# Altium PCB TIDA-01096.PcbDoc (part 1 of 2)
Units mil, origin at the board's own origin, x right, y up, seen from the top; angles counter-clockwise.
Board outline 3070.87 x 3070.87 mil, 2 copper layers (Top Layer, Bottom Layer), stack 62 mil thick; 117 components, 49 nets, 258 pads, 158 vias.
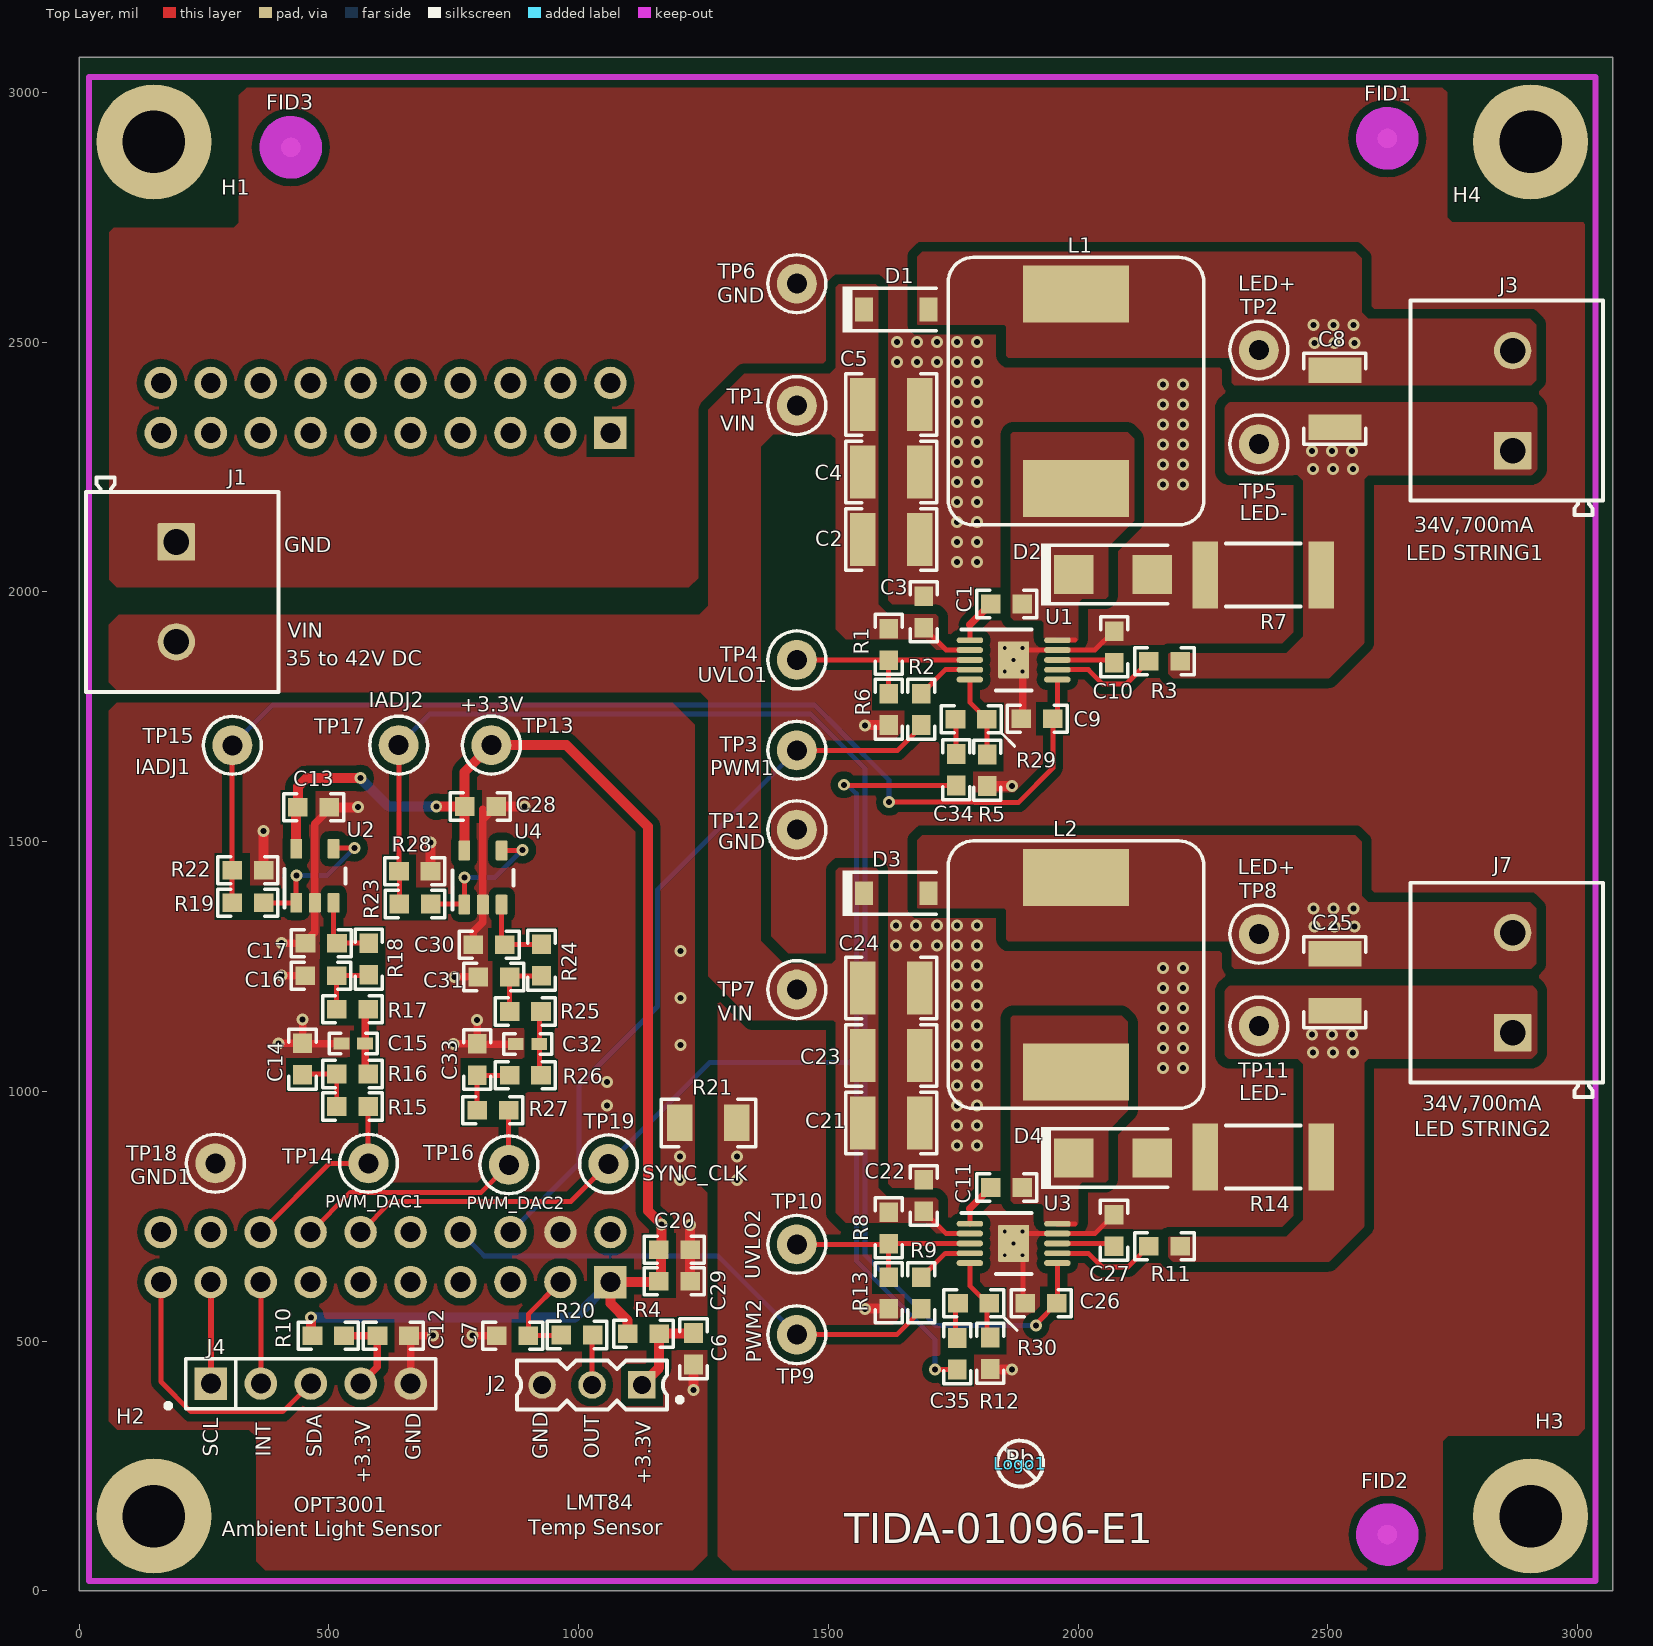
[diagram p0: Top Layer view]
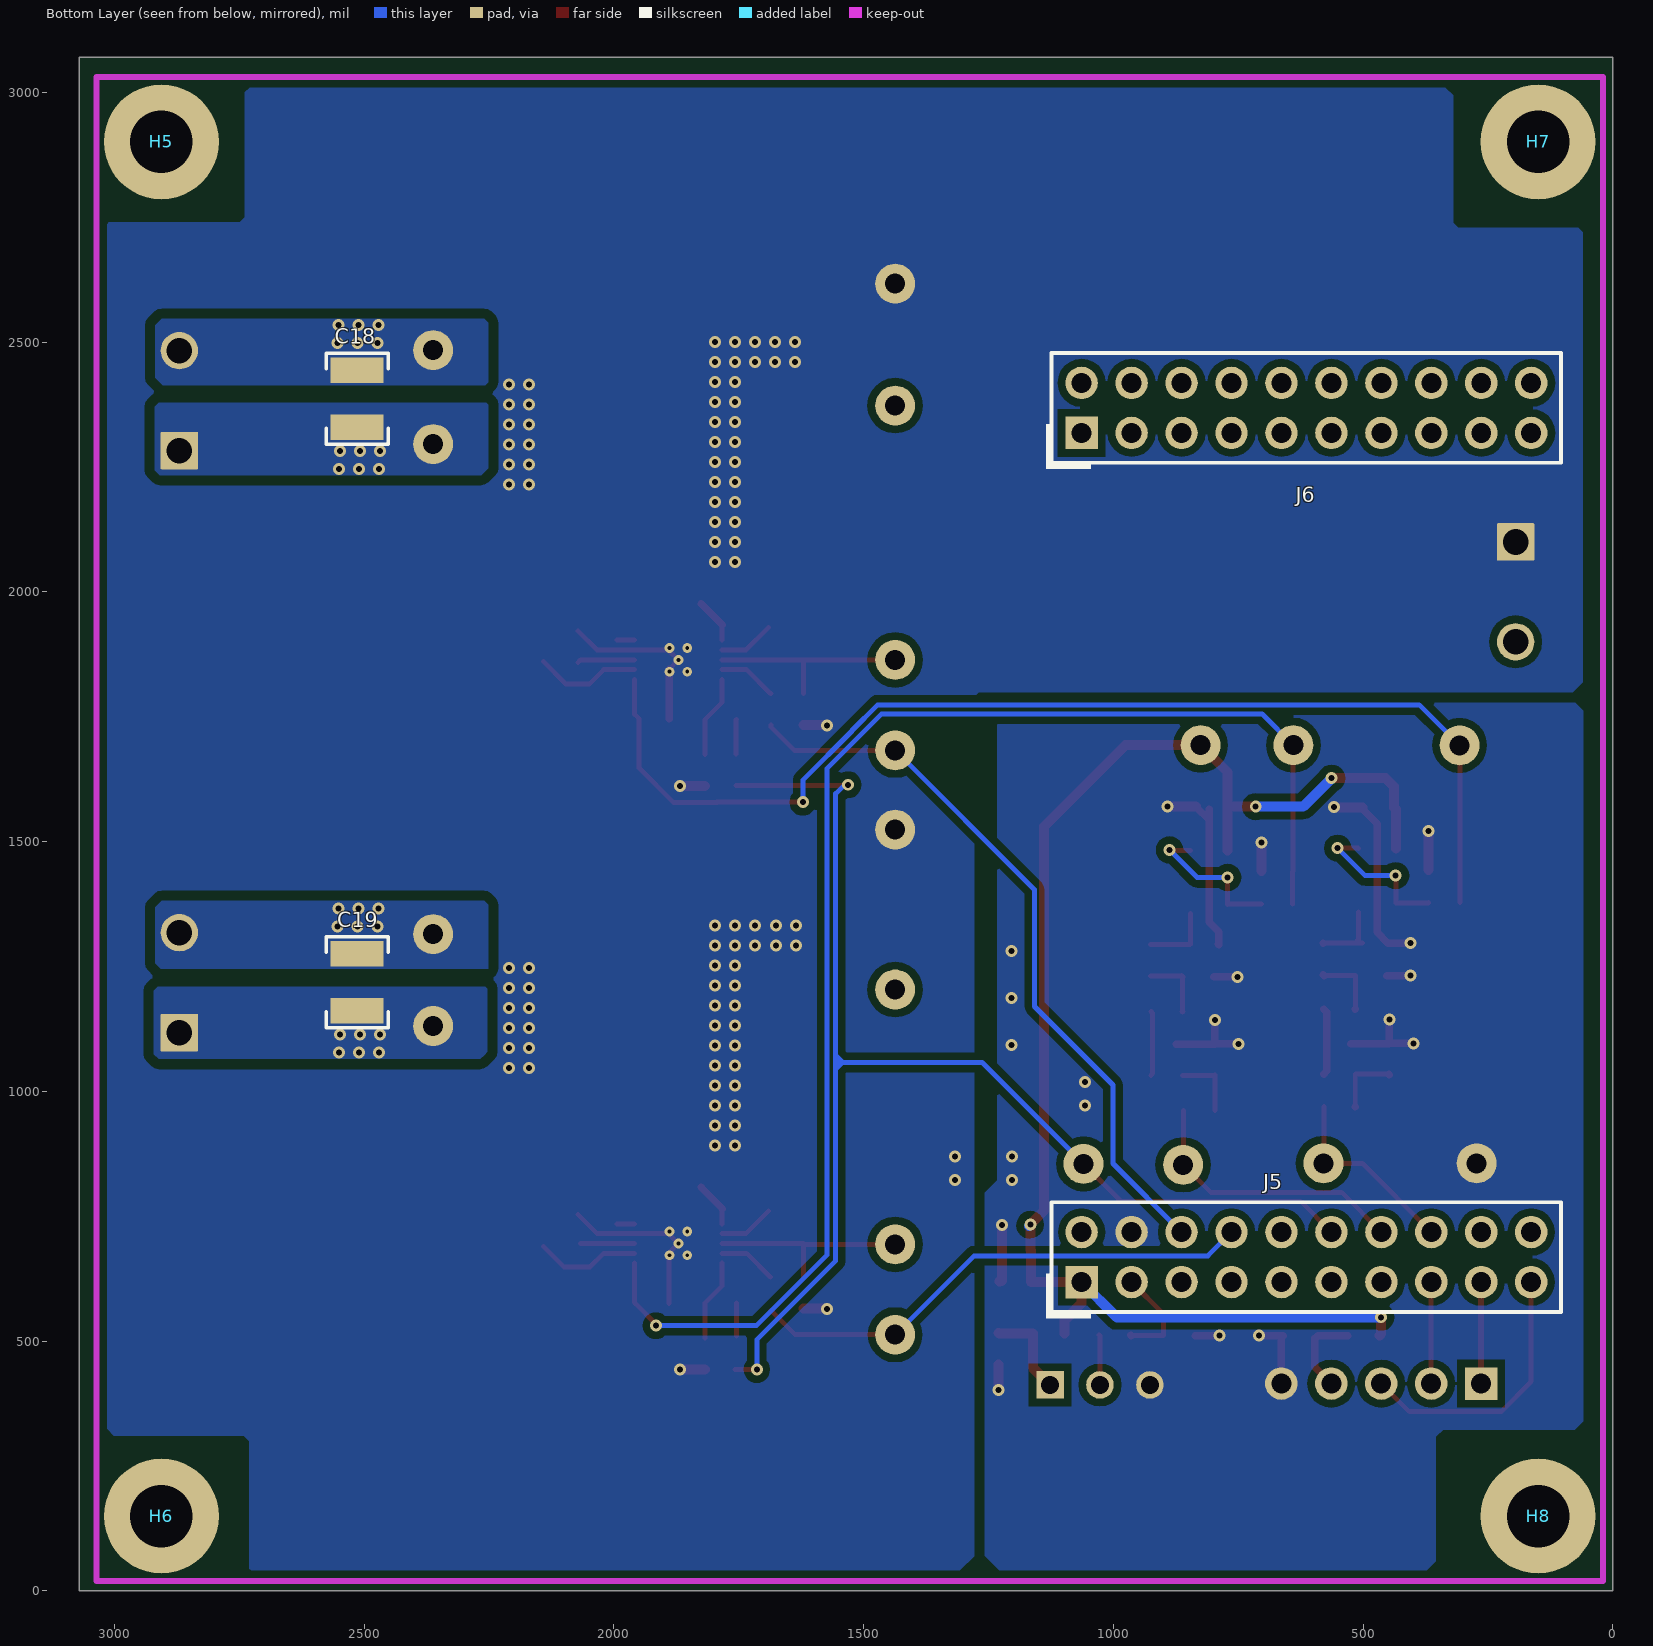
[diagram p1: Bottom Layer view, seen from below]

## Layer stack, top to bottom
Top Solder: solder mask 0.4, Solder Resist, Dk 3.5
Top Layer: signal copper 1.4
Dielectric1: core 59.2, FR-4, Dk 4.8
Bottom Layer: signal copper 1.4
Bottom Solder: solder mask 0.4, Solder Resist, Dk 3.5

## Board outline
0,0 3070.87,0 3070.87,3070.87 0,3070.87

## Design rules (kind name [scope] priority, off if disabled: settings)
AcuteAngle [All] p1: minimum=4.50000000000000E+0001 checktracksonly=FALSE
AssemblyTestPointUsage [All] p1: valid=2
Clearance Clearance_MTG_COPPER [InPadClass('MTG') vs InPoly] p1: gap=40
Clearance "Shape to Shape" [InPolygon vs InPolygon] p2: gap=20
Clearance "shape to all" [InPolygon] p3: gap=15
Clearance Clearance_Boardedge_poly [OnCopper and InPolygon vs IsKeepOut] p4: gap=20
Clearance Clearance_u [InPadClass('U1')] p5: gap=7.8
Clearance "Clearance_via_thr pin" [IsVia vs IsThruPin] p6: gap=8
Clearance "SMD to Via" [IsSMTPin vs IsVia] p7: gap=8
Clearance [All] p8: gap=7.87
DiffPairsRouting DiffPair_DiffPairsRouting [InDifferentialPair ('kan')] p1: maxlimit=10 minlimit=10 mostfreqgap=10 toplayer_minwidth=15 toplayer_maxwidth=15 toplayer_prefwidth=15 bottomlayer_minwidth=15 bottomlayer_maxwidth=15 bottomlayer_prefwidth=15 maxuncoupledlength=500
DiffPairsRouting DiffPair_DiffPairsRouting_1 [InDifferentialPair ('kan')] p2: maxlimit=10 minlimit=10 mostfreqgap=10 toplayer_minwidth=15 toplayer_maxwidth=15 toplayer_prefwidth=15 bottomlayer_minwidth=15 bottomlayer_maxwidth=15 bottomlayer_prefwidth=15 maxuncoupledlength=500
DiffPairsRouting [All] p3: maxlimit=100 minlimit=10 mostfreqgap=10 toplayer_minwidth=15 toplayer_maxwidth=15 toplayer_prefwidth=15 bottomlayer_minwidth=15 bottomlayer_maxwidth=15 bottomlayer_prefwidth=15 maxuncoupledlength=1000
FabricationTestPointUsage TestPointUsage [All] p1: valid=2 allowmultiple=FALSE
FabricationTestpoint Testpoint [All] p1: side=3 testpointundercomponent=TRUE minsize=40 maxsize=100 preferedsize=60 minholesize=0 maxholesize=40 preferedholesize=32 testpointgrid=1 allowsidetop=TRUE allowsidebottom=TRUE usegrid=TRUE gridtolerance=0.01
FanoutControl Fanout_LCC [IsLCC] p1: bgadir=Out bgaviamode=Centered fanoutstyle=Auto fanoutdirection=Alternating viagrid=1 // Fanout_LCC (Default Rule)
FanoutControl Fanout_BGA [IsBGA] p2: bgadir=Out bgaviamode=Centered fanoutstyle=Auto fanoutdirection=Alternating viagrid=1 // Fanout_BGA (Default Rule)
FanoutControl Fanout_Default [All] p4: bgadir=Out bgaviamode=Centered fanoutstyle=Auto fanoutdirection=Alternating viagrid=1 // Fanout_Default (Default Rule)
FanoutControl Fanout_Small [(CompPinCount < 5)] p5: bgadir=Out bgaviamode=Centered fanoutstyle=Auto fanoutdirection=OutThenIn viagrid=1 // Fanout_Small (Default Rule)
HoleSize [All] p1: absolutevalues=TRUE maxlimit=251 minlimit=7 maxpercent=80.000 minpercent=20.000
MatchedLengths DiffPair_MatchedLengths [InDifferentialPair ('kan')] p1: tolerance=1000 checknetsindiffpair=TRUE checkdiffpairvsdiffpair=FALSE checkxsignals=FALSE checkothers=FALSE
MatchedLengths DiffPair_MatchedLengths_1 [InDifferentialPair ('kan')] p2: tolerance=1000 checknetsindiffpair=TRUE checkdiffpairvsdiffpair=FALSE checkxsignals=FALSE checkothers=FALSE
MinimumAnnularRing [All] p1: minimumring=5
MinimumAnnularRing MinimumAnnularRing_ThermalPadVias [IsVia and InAnyComponent] p2: minimumring=5.91
MinimumSolderMaskSliver MinimumSolderMaskSliver_Logo [InComponentClass('Logo') vs InComponentClass('Logo')] p1: minsoldermaskwidth=0.7
MinimumSolderMaskSliver [All] p2: minsoldermaskwidth=3.94
PlaneClearance [All] p1: clearance=15
PlaneConnect [All] p1: planeconnectstyle=Direct reliefexpansion=10 reliefentries=4 reliefconductorwidth=10 reliefairgap=10
PolygonConnect [All] p1: connectstyle=Direct reliefconductorwidth=10 reliefentries=4 polygonreliefangle="90 Angle" airgapwidth=10
RoutingVias RoutingVias_power [InNetClass('POWER')] p1: holewidth=16 width=32 viastyle="Through Hole" minholewidth=7.87 minwidth=19.68 maxholewidth=16 maxwidth=32
RoutingVias ThermalPadVias [IsVia and InAnyComponent] p2: holewidth=8 width=20 viastyle="Through Hole" minholewidth=7.87 minwidth=19 maxholewidth=12 maxwidth=24
RoutingVias [All] p3: holewidth=12 width=24 viastyle="Through Hole" minholewidth=7.87 minwidth=19.68 maxholewidth=16 maxwidth=32
SMDToCorner [All] p1: distance=30000
SilkToSilkClearance [All] p1: silktosilkclearance=5
SilkToSolderMaskClearance SilkscreenOverComponentPads [IsPad] p1: minsilkscreentomaskgap=5 clearancetoexposedcopper=TRUE
SolderMaskExpansion [All] p1: expansion=3
Width Width_power [InNetClass('pwr')] p1: maxlimit=200 minlimit=10 preferedwidth=20
Width [All] p2: maxlimit=100 minlimit=10 preferedwidth=20 checkconnectedcopper=TRUE
16 further rules are at their usual default settings.

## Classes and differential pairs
component class FiducialMark: FID1 FID2 FID3
component class TIDA-01096_Hardware: FID1 FID2 FID3 H1 H2 H3 H4 H5 H6 H7 H8 Logo1 ZZ1 ZZ2 ZZ3 ZZ4
pad class U1: U1-1 U1-2 U1-3 U1-4 U1-5 U1-6 U1-7 U1-8 U1-9 U1-10 U1-11 U3-1 U3-2 U3-3 U3-4 U3-5 U3-6 U3-7 U3-8 U3-9 U3-10 U3-11
component class AssemblyNote: ZZ1 ZZ2 ZZ3 ZZ4
component class Header: J2 J4 J5 J6
pad class MTG: H1-1 H2-1 H3-1 H4-1 H5-0 H6-0 H7-0 H8-0
component class TIDA-01096_Sheet1: C1 C2 C3 C4 C5 C6 C7 C8 C9 C10 C11 C12 C13 C14 C15 C16 C17 C18 C19 C20 C21 C22 C23 C24 C25 C26 C27 C28 C29 C30 C31 C32 C33 C34 C35 D1 D2 D3 D4 J1 J2 J3 J4 J5 J6 J7 L1 L2 R1 R2 R3 R4 R5 R6 R7 R8 R9 R10 R11 R12 R13 R14 R15 R16 R17 R18 R19 R20 R21 R22 R23 R24 R25 R26 R27 R28 R29 R30 TP1 TP2 TP3 TP4 TP5 TP6 TP7 TP8 TP9 TP10 TP11 TP12 TP13 TP14 TP15 TP16 TP17 TP18 TP19 U1 U2 U3 U4

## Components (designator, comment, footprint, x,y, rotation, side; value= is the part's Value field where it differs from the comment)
C1 "GRM188R71E104KA01D" 0603 1857,1976 r0 top
C2 "GRJ32DC72A475KE11L" 1210_220 1626,2105 r0 top
C3 "GCM188R72A103KA37D" 0603 1691,1960 r90 top
C4 "GRJ32DC72A475KE11L" 1210_220 1626,2240 r0 top
C5 "GRJ32DC72A475KE11L" 1210_220 1626,2375 r0 top
C6 "GRT188C81A106ME13D" 0603 1230,485 r270 top
C7 "GCM188R71H104KA57D" 0603 868,511 r180 top
C8 "GRM32ER72A225KA35L" 1210_270 2514,2387 r270 top
C9 "GRM188R71E103KA01D" 0603 1918,1746 r180 top
C10 "GCM188R71H104KA57D" 0603 2072.27,1890 r90 top
C11 "GRM188R71E104KA01D" 0603 1857,807.8 r0 top
C12 "GRT188C81A106ME13D" 0603 629,511 r0 top
C13 "GCM188R71H104KA57D" 0603 469.63,1568.84 r0 top
C14 "GRM188R71A474KA61D" 0603 447.48,1064.79 r90 top
C15 "GRM155R71A473KA01D" 0402 549,1096 r180 top
C16 "GCM188R72A103KA37D" 0603 484.48,1231.79 r180 top
C17 "C0603X471K5RACTU" 0603 485,1297 r180 top
C18 "GRM32ER72A225KA35L" 1210_270 2514,2387 r270 bottom
C19 "GRM32ER72A225KA35L" 1210_270 2514,1218.8 r270 bottom
C20 "GRT188C81A106ME13D" 0603 1192,683 r0 top
C21 "GRJ32DC72A475KE11L" 1210_220 1626,936.8 r0 top
C22 "GCM188R72A103KA37D" 0603 1691,791.8 r90 top
C23 "GRJ32DC72A475KE11L" 1210_220 1626,1071.8 r0 top
C24 "GRJ32DC72A475KE11L" 1210_220 1626,1206.8 r0 top
C25 "GRM32ER72A225KA35L" 1210_270 2514,1218.8 r270 top
C26 "GRM188R71E103KA01D" 0603 1926,576 r180 top
C27 "GCM188R71H104KA57D" 0603 2072,721.8 r90 top
C28 "GCM188R71H104KA57D" 0603 803.65,1570.3 r0 top
C29 "GRM188R71E104KA01D" 0603 1191.99,620.2 r0 top
C30 "C0603X471K5RACTU" 0603 821,1294 r180 top
C31 "GCM188R72A103KA37D" 0603 830.5,1229.25 r180 top
C32 "GRM155R71A473KA01D" 0402 898,1095 r180 top
C33 "GRM188R71A474KA61D" 0603 797,1064 r90 top
C34 "C0603X471K5RACTU" 0603 1756,1644 r270 top
C35 "C0603X471K5RACTU" 0603 1758,475 r270 top
D1 "MBR0580-TP" SOD-123 1636,2565 r0 top
D2 "SK310AFL-TP" SMA 2070,2035 r0 top
D3 "MBR0580-TP" SOD-123 1636,1396.8 r0 top
D4 "SK310AFL-TP" SMA 2070,866.8 r0 top
FID1 "Fiducial" Fiducial10-30 2619,2908 r0 top
FID2 "Fiducial" Fiducial10-30 2619,113 r90 top
FID3 "Fiducial" Fiducial10-30 424,2890 r90 top
H1 "PMSSS 440 0025 PH" B_F_PMSSS4400025PH 150,2901 r0 top
H2 "PMSSS 440 0025 PH" B_F_PMSSS4400025PH 150,150 r0 top
H3 "PMSSS 440 0025 PH" B_F_PMSSS4400025PH 2906,150 r0 top
H4 "PMSSS 440 0025 PH" B_F_PMSSS4400025PH 2906,2901 r0 top
H5 "1902E" Keystone_1902E 2906,2901 r180 bottom
H6 "1902E" Keystone_1902E 2906,150 r180 bottom
H7 "1902E" Keystone_1902E 150,2901 r180 bottom
H8 "1902E" Keystone_1902E 150,150 r180 bottom
J1 "1715721" PhoenixContact_1715721 195,2000 r270 top
J2 "SL 11 112 03G" Fischer_SL-11-112-03G 1027,412.43 r180 top
J3 "1715721" PhoenixContact_1715721 2870,2383 r90 top
J4 "TSW-105-07-G-S" TSW-105-07-G-S 464,415.2 r0 top
J5 "PEC10DAAN" SULLINS_PEC10DAAN 613.75,668.43 r90 bottom locked
J6 "PEC10DAAN" SULLINS_PEC10DAAN 613.75,2368.43 r90 bottom locked
J7 "1715721" PhoenixContact_1715721 2870,1217.8 r90 top
L1 "744770133" WE-PD-XL 1996,2402 r90 top
L2 "744770133" WE-PD-XL 1996,1233.8 r90 top
Logo1 "Pb-Free Symbol" Pb-Free_Overlay_Small 1884,255 r0 top
R1 "CRCW0603120KFKEA" 0603 1621,1895 r90 top
R2 "CRCW06031K00FKEA" 0603 1686,1765 r90 top
R3 "CRCW06031K00FKEA" 0603 2173,1861 r180 top
R4 "RC0603FR-07100RL" 0603 1130,515 r180 top
R5 "CRCW0603191KFKEA" 0603 1818,1643 r90 top
R6 "CRCW06034K99FKEA" 0603 1621,1765 r90 top
R7 "CSRN2512FK50L0CT-ND" 2512 2371,2034 r0 top
R8 "CRCW0603120KFKEA" 0603 1621,726.8 r90 top
R9 "CRCW06031K00FKEA" 0603 1686,596.8 r90 top
R10 "RC0603FR-07100RL" 0603 499,511 r0 top
R11 "CRCW06031K00FKEA" 0603 2173,690 r180 top
R12 "CRCW0603191KFKEA" 0603 1824,476 r90 top
R13 "CRCW06034K99FKEA" 0603 1621,596.8 r90 top
R14 "CSRN2512FK50L0CT-ND" 2512 2371,869 r0 top
R15 "CRCW0603866RFKEA" 0603 547.48,969.79 r180 top
R16 "CRCW06038K66FKEA" 0603 547.48,1034.79 r0 top
R17 "CRCW060386K6FKEA" 0603 547.48,1164.79 r180 top
R18 "CRCW0603866KFKEA" 0603 580,1265 r90 top
R19 "CRCW060333K0FKEA" 0603 338.18,1377.82 r180 top
R20 "RC0603FR-071K5L" 0603 997,512.43 r0 top
R21 "CRCW12060000Z0EA" 1206 1260,937 r0 top
R22 "CRCW06032K20FKEA" 0603 338.18,1443.05 r0 top
R23 "CRCW060333K0FKEA" 0603 672.65,1375.3 r180 top
R24 "CRCW0603866KFKEA" 0603 926,1263 r90 top
R25 "CRCW060386K6FKEA" 0603 893.5,1160.25 r180 top
R26 "CRCW06038K66FKEA" 0603 893.5,1032.25 r0 top
R27 "CRCW0603866RFKEA" 0603 828.5,962.25 r180 top
R28 "CRCW06032K20FKEA" 0603 672.15,1441.05 r0 top
R29 "CRCW06034K02FKEA" 0603 1786,1745 r0 top
R30 "CRCW06034K02FKEA" 0603 1791,575.8 r0 top
TP1 "5000" Keystone5000 1437,2373 r90 top
TP2 "5000" Keystone5000 2362,2484 r90 top
TP3 "5000" Keystone5000 1437,1683 r90 top
TP4 "5000" Keystone5000 1437,1864 r90 top
TP5 "5000" Keystone5000 2362,2296 r90 top
TP6 "5000" Keystone5000 1437,2617 r90 top
TP7 "5000" Keystone5000 1437,1204 r90 top
TP8 "5000" Keystone5000 2362,1314.96 r90 top
TP9 "5000" Keystone5000 1437,513 r90 top
TP10 "5000" Keystone5000 1437,694 r90 top
TP11 "5000" Keystone5000 2362,1130.96 r90 top
TP12 "5000" Keystone5000 1437,1524 r90 top
TP13 "5000" Keystone5000 825.5,1693.25 r270 top
TP14 "5000" Keystone5000 579.5,856.25 r270 top
TP15 "5000" Keystone5000 307,1693 r90 top
TP16 "5000" Keystone5000 860.5,853.25 r270 top
TP17 "5000" Keystone5000 640,1693.25 r270 top
TP18 "5000" Keystone5000 273,856.25 r90 top
TP19 "5000" Keystone5000 1060,855 r90 top
U1 "TPS92513HVDGQR" DGQ0010D_N 1871,1864 r0 top
U2 "OPA376AIDBVR" DBV0005A_N 472.21,1431.82 r90 top
U3 "TPS92513HVDGQR" DGQ0010D_N 1871,695.8 r0 top
U4 "OPA376AIDBVR" DBV0005A_N 808.65,1428.3 r90 top
ZZ1 "This Assembly Note is for PCB labels only" AssemblyNoteLabel 210.18,3837.51 r0 top
ZZ2 "These assemblies are ESD sensitive, ESD precautions shall be observed." AssemblyNote 1561.9,6384.61 r0 top
ZZ3 "These assemblies must be clean and free from flux and all contaminants. Use of no clean flux is not acceptable." AssemblyNote 1561.9,6299.61 r0 top
ZZ4 "These assemblies must comply with workmanship standards IPC-A-610 Class 2, unless otherwise specified." AssemblyNote 1561.9,6224.61 r0 top

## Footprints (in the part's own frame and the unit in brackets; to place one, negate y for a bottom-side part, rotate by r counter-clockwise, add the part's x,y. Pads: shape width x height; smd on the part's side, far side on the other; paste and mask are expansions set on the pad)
0402 [mm] "0402 from SM-752 data"
  rect 0.8x0.6 smd: 1(-0.6,0) 2(0.6,0)
  silkscreen extent -1.22,-0.52 1.22,0.52, body extent -0.55,-0.3 0.55,0.3, height 0.6
0603 [mm] "0603 from SM-752 data"
  rect 1x0.95 smd: 1(-0.8,0) 2(0.8,0)
  silkscreen extent -1.52,-0.69 1.52,0.69, body extent -0.87,-0.47 0.87,0.47, height 1
1206 [mm] "1206 from SM-752 data"
  rect 1.3x1.85 smd: 1(-1.45,0) 2(1.45,0)
  silkscreen extent -2.4,-1.21 2.4,1.21, body extent -1.7,-0.9 1.7,0.9, height 1.35
1210_220 [mm] "1210"
  rect 1.3x2.7 smd: 1(-1.45,0) 2(1.45,0)
  silkscreen extent -2.32,-1.57 2.32,1.57, body extent -1.7,-1.35 1.7,1.35, height 2.2
1210_270 [mm] "1210"
  rect 1.3x2.7 smd: 1(-1.45,0) 2(1.45,0)
  silkscreen extent -2.32,-1.57 2.32,1.57, body extent -1.7,-1.35 1.7,1.35, height 2.7
2512 [mm] "Chip Resistor, Body 6.3x3.2mm, IPC Medium Density"
  rect 1.3x3.4 smd: 1(-2.95,0) 2(2.95,0)
  silkscreen extent -1.9,-1.6 1.9,1.6, body extent -3.22,-1.67 3.22,1.67, height 0.71
AssemblyNote [mil] "Assembly Note"
AssemblyNoteLabel [mil] "Assembly Note for PCB Labels"
B_F_PMSSS4400025PH [mil] "MACHINE SCREW PAN PHILLIPS 4-40"
  round 230 hole 125: 1(0,0)
  body extent -109,-109 110,110, height 79
DBV0005A_N [mm] "SOT23, 5-Leads, Body 2.9x1.6mm, Pitch 0.95mm, Lead Span 2.8mm, IPC Medium Density"
  rrect17% 1x0.6 smd: 1(-1.375,0.95) 2(-1.375,0) 3(-1.375,-0.95) 4(1.375,-0.95) 5(1.375,0.95)
  silkscreen extent -1.63,-1.55 0.38,1.55, body extent -1.42,-1.46 1.42,1.46, height 1.09
DGQ0010D_N [mm] "TSSOP, 10-Leads, Body 3x3mm, Pitch 0.5mm, Thermal Pad 1.88x1.57mm, IPC Medium Density"
  rrect100% 1.35x0.3 smd: 1(-2.225,1) 2(-2.225,0.5) 3(-2.225,0) 4(-2.225,-0.5) 5(-2.225,-1) 6(2.225,-1) 7(2.225,-0.5) 8(2.225,0) 9(2.225,0.5) 10(2.225,1)
  rrect6% 1.57x1.88 smd: 11(0,0)
  silkscreen extent -2.65,-1.55 0.9,1.55, body extent -2.46,-1.5 2.46,1.5, height 1.1
Fiducial10-30 [mm]
  round 1 smd mask+1: 1(0,0)
  Top Layer keep-out circle w1.678: c0,0 r0.75
Fischer_SL-11-112-03G [mm] "TH, 3-Leads, Body 2.5x7.62mm, Pitch 2.54mm"
  rect 1.4x1.4 hole 0.9: 1(-2.54,0)
  round 1.4 hole 0.9: 2(0,0) 3(2.54,0)
  silkscreen extent -4.59,-1.25 3.81,1.25, body extent -3.81,-1.25 3.81,1.25, height 8.4
Keystone5000 [mil] "For Keystone 500x miniature loop terminals"
  round 80 hole 40: 1(0,0)
  silkscreen extent -58,-58 58,58, body extent -49,-49 49,49, height 182
Keystone_1902E [mil] "Hex Standoff, 4-40 threaded, nylon"
  round 1 on Mech4: 0(0,0)
  body extent -145,-126 146,126, height 1001
Pb-Free_Overlay_Small [mil]
  silkscreen extent -46,-46 46,46
PhoenixContact_1715721 [mm] "Phoenix Contact 1715721 used on LM3445 design from Longmont"
  rrect5% 1.905x1.905 hole 1.3: 1(-2.54,0)
  round 1.9 hole 1.3: 2(2.54,0)
  silkscreen extent -5.82,-4.6 5.08,5.2, body extent -5.82,-4.6 5.08,5.2, height 14.2
SMA [mm] "Molded Diode, 2-Leads, Body 4.3x2.6mm, IPC Medium Density, based on OnSemi component dimensions and land pattern"
  rect 2x2 smd: 1(-2,0) 2(2,0)
  silkscreen extent -3.66,-1.57 2.79,1.57, body extent -2.6,-1.3 2.6,1.3, height 2.42
SOD-123 [mm] "On Semi recommended land pattern"
  rect 0.915x1.22 smd: 1(-1.637,0) 2(1.637,0)
  silkscreen extent -2.74,-1.17 2.03,1.17, body extent -1.93,-0.9 1.93,0.9, height 1.35
SULLINS_PEC10DAAN [mm] "SULLINS"
  rect 1.65x1.65 hole 1.016: 1(-1.27,11.43)
  round 1.65 hole 1.016: 2(1.27,11.43) 3(-1.27,8.89) 4(1.27,8.89) 5(-1.27,6.35) 6(1.27,6.35) 7(-1.27,3.81) 8(1.27,3.81) 9(-1.27,1.27) 10(1.27,1.27) 11(-1.27,-1.27) 12(1.27,-1.27) 13(-1.27,-3.81) 14(1.27,-3.81) 15(-1.27,-6.35) 16(1.27,-6.35) 17(-1.27,-8.89) 18(1.27,-8.89) 19(-1.27,-11.43) 20(1.27,-11.43)
  silkscreen extent -3.11,-12.96 2.79,13.25, body extent -2.79,-12.96 2.79,12.96, height 9.08
TSW-105-07-G-S [mm] "Samtec 100mil, 1x5, 230 mil above insulator"
  rect 1.65x1.65 hole 1.016 mask+0.076: 1(-5.08,0)
  round 1.65 hole 1.016 mask+0.076: 2(-2.54,0) 3(0,0) 4(2.54,0) 5(5.08,0)
  silkscreen extent -7.37,-1.27 6.35,1.27, body extent -6.35,-1.27 6.35,1.27, height 8.38
WE-PD-XL [mm] "Wurth Elektronik recommended land pattern"
  rect 2.9x5.4 smd: 1(-4.95,0) 2(4.95,0)
  silkscreen extent -6.8,-6.5 6.8,6.5, body extent -6.15,-6.17 6.15,6.12, height 8

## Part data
C1 C11 C29: "CAP, CERM, 0.1 µF, 25 V, +/- 10%, X7R, 0603"
C2 C4 C5 C21 C23 C24: library part C3225X7S2A475K200AB, "4.7µF ±10% 100V X7S Ceramic Capacitor -55°C ~ 125°C Surface Mount, MLCC 1210 (3225 Metric) 0.126\" L x 0.098\" W (3.20mm x 2.50mm)"
C3 C22: library part 06031C103KAT2A, "10000pF ±10% 100V X7R Ceramic Capacitor -55°C ~ 125°C Surface Mount, MLCC 0603 (1608 Metric) 0.063\" L x 0.031\" W (1.60mm x 0.80mm)"
C6 C12 C20: "CAP, CERM, 10 µF, 10 V, +/- 20%, X6S, AEC-Q200 Grade 2, 0603"
C7 C10 C13 C27 C28: "CAP, CERM, 0.1 µF, 50 V, +/- 10%, X7R, 0603"
C8 C18 C19 C25: "CAP, CERM, 2.2 µF, 100 V, +/- 10%, X7R, 1210"
C9 C26: "CAP, CERM, 0.01 µF, 25 V, +/- 10%, X7R, 0603"
C14 C33: "CAP, CERM, 0.47 µF, 10 V, +/- 10%, X7R, 0603"
C15 C32: "CAP, CERM, 0.047 µF, 10 V, +/- 10%, X7R, 0402"
C16 C31: library part GCM188R71H472KA37D, "10000pF ±10% 100V X7R Ceramic Capacitor -55°C ~ 125°C Surface Mount, MLCC 0603 (1608 Metric) 0.063\" L x 0.031\" W (1.60mm x 0.80mm)"
C17 C30 C34 C35: "CAP, CERM, 470 pF, 50 V, +/- 10%, X7R, 0603"
D1 D3: "Diode, Schottky, 80 V, 0.5 A, SOD-123"
D2 D4: library part CDBA280-G, "DIODE SCHOTTKY 100V 3A DO221AC"
FID1 FID2 FID3: "Fiducial mark.  There is nothing to buy or mount."
H1 H2 H3 H4: "MACHINE SCREW PAN PHILLIPS 4-40"
H5 H6 H7 H8: "Standoff, Hex, 1\"L #4-40 Nylon"
J1 J3 J7: "Terminal Block, 5.08 mm, 2x1, TH"
J2: "Header, 2.54mm, 3x1, Gold, TH"
J4: "Header, 100mil, 5x1, Gold, TH"
J5 J6: "Header, 100mil, 10x2, TH"
L1 L2: "Inductor, Shielded Drum Core, Ferrite, 33uH, 3.2A, 0.047 ohm, SMD"
Logo1: library part Pb-Free
R1 R8: library part RC0603FR-07120KL, "RES SMD 120K OHM 1% 1/10W 0603"
R2 R3 R9 R11: "RES, 1.00 k, 1%, 0.1 W, 0603"
R4 R10: "RES, 100, 1%, 0.1 W, 0603"
R5 R12: "RES, 191 k, 1%, 0.1 W, 0603"
R6 R13: "RES, 4.99 k, 1%, 0.1 W, 0603"
R7 R14: library part CSRN2512FK50L0, "RES, 0.05, 1%, 2 W, 2512"
R15 R27: "RES, 866, 1%, 0.1 W, 0603"
R16 R26: "RES, 8.66 k, 1%, 0.1 W, 0603"
R17 R25: "RES, 86.6 k, 1%, 0.1 W, 0603"
R18 R24: "RES, 866 k, 1%, 0.1 W, 0603"
R19 R23: "RES, 33.0 k, 1%, 0.1 W, 0603"
R20: "RES, 1.50 k, 1%, 0.1 W, 0603"
R21: "RES, 0, 5%, 0.25 W, 1206"
R22 R28: library part RC0603FR-072K2L, "RES SMD 2.2K OHM 1% 1/10W 0603"
R29 R30: "RES, 4.02 k, 1%, 0.1 W, 0603"
TP1 TP2 TP3 TP4 TP5 TP6 TP7 TP8 TP9 TP10 TP11 TP12 TP13 TP14 TP15 TP16 TP17 TP18 TP19: "Test Point, Miniature, Red, TH"
U1 U3: "1.5A Buck LED Driver with Integrated Analog Current Adjust, DGQ0010D"
U2 U4: "Precision, Low Noise, Low Iq Operational Amplifier, 2.2 to 5.5 V, -40 to 125 degC, 5-pin SOT23 (DBV0005A), Green (RoHS & no Sb/Br)"
ZZ1: library part AssemblyNoteLabel
ZZ2 ZZ3 ZZ4: library part AssemblyNote

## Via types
v1: diameter 24, hole 12, Top Layer to Bottom Layer, tented both sides, 148 vias
v2: diameter 19.68, hole 7.87, Top Layer to Bottom Layer, tented both sides, 10 vias

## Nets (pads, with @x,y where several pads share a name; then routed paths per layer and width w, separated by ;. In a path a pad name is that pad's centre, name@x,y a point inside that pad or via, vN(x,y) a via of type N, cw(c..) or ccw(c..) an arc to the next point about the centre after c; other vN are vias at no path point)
+3.3V: C13.1 C20.1 C28.1 C29.1 J5.1 R4.2 R10.1 TP13.1 U2.5 U4.5 | length 2915.1
  Top Layer w20: U2.5@434.81,1485.96 434.81,1565.51 C13.1@438.13,1568.84 438.13,1610.03 455.15,1627.05 v1(563.15,1627.05) ; v1(464,548) 464,514.5 R10.1@467.5,511 ; v1(715.18,1570.09) 715.38,1570.3 C28.1@772.16,1570.3 771.25,1569.39 U4.5@771.25,1482.43 ; C28.1@772,1573.25 772,1639.75 TP13.1@825.5,1693.25 975.75,1693.25 1139,1530 1139,761 v1(1166.5,733.5) 1166.5,683 1165.5,682 1165.5,619.2 1164.73,618.43 J5.1@1063.75,618.43 1063.75,575.84 1098.5,541.08 R4.2@1098.5,515
  Bottom Layer w20: v1(464,548) 993.32,548 J5.1@1063.75,618.43 ; v1(563.15,1627.05) 620.11,1570.09 v1(715.18,1570.09) ; v1(1166.5,733.5) v1@1169,731
+5V: J5.2
DIO4_SCL: J4.1 J5.17 | length 203.3
  Top Layer w12: J5.17@263.75,618.43 264,618.17 J4.1@264,415.2
DIO5_SDA: J4.3 J5.19 | length 547.7
  Top Layer w10: J5.19@163.75,618.43 163.75,419.25 224,359 407.8,359 J4.3@464,415.2
DIO21_INT: J4.2 J5.15 | length 203.3
  Top Layer w10: J5.15@363.75,618.43 364,618.17 J4.2@364,415.2
DIO23_TEMP: C7.1 J5.3 R20.1 | length 200.6
  Top Layer w10: J5.3@963.75,618.43 899.5,554.18 C7.1@899.5,511 R20.1@964.08,511
  Top Layer w15: R20.1@964.08,511 R20.1@965.5,512.43
GND: C2.2 C3.2 C4.2 C5.2 C9.2 C10.2 C21.2 C22.2 C23.2 C24.2 C26.2 C27.2 D2.2 D4.2 J1.1 R5.1 R6.1 R7.1 R12.1 R13.1 R14.1 R21.2 TP6.1 TP12.1 U1.9 U1.11 U3.9 U3.11 | length 897.5
  Top Layer w10: U1.11@1889.5,1845.5 v2(1871,1864) 1890.69,1883.69 U1.9@1958.6,1883.69 2033.69,1883.69 2071.5,1921.5 C10.2@2072.27,1921.5 ; C26.2@1890.01,576 1890.01,676.79 v2(1871,695.8) 1890.69,715.49 U3.9@1958.6,715.49 2033.69,715.49 2071.5,753.3 C27.2@2072.27,753.3
  Top Layer w15: C9.2@1889.5,1746 U1.11@1889.5,1845.5
  Top Layer w20: v1@1573.5,565.3 R13.1@1621,565.3 ; v1@1573.5,1733.5 R6.1@1621,1733.5 ; R12.1@1818,443.3 v1(1867.5,443.3) ; R5.1@1818,1611.5 v1(1867.5,1611.5)
  other v1: 1573,564.8 1317.17,823 1317.17,870 1758,891.8 1798,891.8 1758,931.8 1798,931.8 1758,971.8 1798,971.8 1758,1011.8 1798,1011.8 2170,1046.8 2210,1046.8 1758,1051.8 1798,1051.8 2170,1086.8 2210,1086.8 1758,1091.8 1798,1091.8 2170,1126.8 2210,1126.8 1758,1131.8 1798,1131.8 2170,1166.8 2210,1166.8 1758,1171.8 1798,1171.8 2170,1206.8 2210,1206.8 1758,1211.8 1798,1211.8 2170,1246.8 2210,1246.8 1758,1251.8 1798,1251.8 1636,1291.8 1676,1291.8 1718,1291.8 1758,1291.8 1798,1291.8 1636,1331.8 1676,1331.8 1718,1331.8 1758,1331.8 1798,1331.8 1573,1733 1758,2060 1798,2060 1758,2100 1798,2100 1758,2140 1798,2140 1758,2180 1798,2180 2170,2215 2210,2215 1758,2220 1798,2220 2170,2255 2210,2255 1758,2260 1798,2260 2170,2295 2210,2295 1758,2300 1798,2300 2170,2335 2210,2335 1758,2340 1798,2340 2170,2375 2210,2375 1758,2380 1798,2380 2170,2415 2210,2415 1758,2420 1798,2420 1638,2460 1678,2460 1718,2460 1758,2460 1798,2460 1638,2500 1678,2500 1718,2500 1758,2500 1798,2500
  other v2: 1853.28,672.18 1888.72,672.18 1853.28,719.42 1888.72,719.42 1853.28,1840.38 1888.72,1840.38 1853.28,1887.62 1888.72,1887.62
GND1: C6.2 C7.2 C12.2 C13.2 C14.2 C15.2 C16.2 C17.2 C20.2 C28.2 C29.2 C30.2 C31.2 C32.2 C33.2 J2.3 J4.5 J5.4 R21.1 R22.2 R28.2 TP18.1 U2.2 U4.2 | length 1701.5
  Top Layer w15: v1(399.7,1096.29) C14.2@447.48,1096.29 ; v1(405.21,1231.79) C16.2@452.98,1231.79 ; v1(405.21,1296.79) 450.57,1296.79 472.21,1318.43 U2.2@472.21,1377.69 472.21,1536.1 501.13,1565.02 C13.2@501.13,1568.84 ; v1(447.48,1144.06) C14.2@447.48,1096.29 ; C15.2@525.38,1096 447.77,1096 C14.2@447.48,1096.29 ; C12.2@660.5,511 v1(709,511) ; J4.5@664,415.2 C12.2@664,507.5 ; v1(749.23,1095.5) C33.2@797,1095.5 ; v1(751.23,1229.25) C31.2@799,1229.25 ; v1(788,511) C7.2@836.5,511 ; C30.2@789.75,1294.25 C30.2@789.5,1294 789.5,1319.85 808.65,1339 U4.2@808.65,1374.17 808.65,1543.8 ; v1(797,1143.27) C33.2@797,1095.5 ; 808.65,1564.8 808.65,1543.8 ; C28.2@835.15,1570.3 808.65,1543.8 ; C32.2@874.38,1095 797.5,1095 C33.2@797,1095.5
  Top Layer w20: v1(369.47,1521.03) 369.67,1520.82 R22.2@369.67,1443.05 ; v1(405.21,1296.79) v1@405.41,1297 ; C13.2@501.13,1568.84 557.9,1568.84 v1(558.11,1569.05) ; v1(703.44,1498.03) 703.65,1497.82 R28.2@703.65,1441.05 ; C28.2@835.15,1570.3 891.92,1570.3 v1(892.13,1570.51) ; v1(1223,733) 1223,702.18 1223.5,701.68 C29.2@1223.49,620.2 ; C29.2@1228.5,619.2 C29.2@1228.5,620.2 ; v1(1230,402) C6.2@1230,453.5
  other v1: 1203,823 1203,870 1057,972 1057,1019 1204,1093 1204,1187 1204,1281
IADJ1: C9.1 R19.2 R22.1 TP15.1 U1.6 | length 2308
  Top Layer w10: R19.2@306.68,1377.82 R22.1@306.68,1443.05 306.68,1692.38 306.53,1692.53 TP15.1@307,1693 ; v1(1622,1579) 1793.91,1579 1793.97,1578.94 1880.94,1578.94 1949.5,1647.5 C9.1@1949.5,1746 1958.6,1755.1 U1.6@1958.6,1824.63
  Bottom Layer w10: TP15.1@307,1693 388,1774 1472.05,1774 1523.52,1722.52 1523.52,1721.75 1622,1623.28 v1(1622,1579)
IADJ2: C26.1 R23.2 R28.1 TP17.1 U3.6 | length 2841.4
  Top Layer w10: TP17.1@640,1693.25 640.66,1692.59 R28.1@640.66,1441.05 641.16,1440.55 R23.2@641.16,1375.3 ; v1(1915.99,531.01) 1915.99,534.5 C26.1@1957.5,576 1958.6,577.1 U3.6@1958.6,656.43
  Bottom Layer w10: TP17.1@640,1693.25 702.75,1756 1464,1756 1573.87,1646.13 1573.87,672.13 1714.99,531.01 v1(1915.99,531.01)
NetC1_1: C1.1 U1.1 | length 90.1
  Top Layer w10: U1.1@1783.4,1903.37 1783.4,1933.9
  Top Layer w15: 1783.4,1933.9 C1.1@1825.5,1976
NetC1_2: C1.2 D2.1 L1.1 U1.10 | length 35.4
  Top Layer w10: U1.10@1958.6,1903.37 1994,1903.37
NetC2_1: C2.1 C3.1 C4.1 C5.1 C21.1 C22.1 C23.1 C24.1 D1.1 D3.1 J1.2 R1.2 R8.2 TP1.1 TP7.1 U1.2 U3.2 | length 221.9
  Top Layer w10: C22.1@1691,760.3 1735.82,715.49 U3.2@1783.4,715.49 ; C3.1@1691,1928.5 1735.82,1883.69 U1.2@1783.4,1883.69
NetC6_1: C6.1 J2.1 R4.1 | length 186
  Top Layer w20: J2.1@1127,412.43 1161.5,446.92 R4.1@1161.5,515 1228.5,515 C6.1@1230,516.5
NetC8_1: C8.1 C18.1 D1.2 J3.2 L1.2 TP2.1
  other v1: 2473,2498 2513,2498 2553,2498 2471,2534 2511,2534 2551,2534
NetC8_2: C8.2 C18.2 J3.1 R3.1 R7.2 TP5.1
  other v1: 2470,2246 2510,2246 2550,2246 2468,2282 2508,2282 2548,2282
NetC10_1: C10.1 U1.8 | length 115.9
  Top Layer w10: U1.8@1958.6,1864 2066.77,1864 C10.1@2072.27,1858.5
NetC11_1: C11.1 U3.1 | length 90.1
  Top Layer w10: U3.1@1783.4,735.17 1783.4,765.7
  Top Layer w15: 1783.4,765.7 C11.1@1825.5,807.8
NetC11_2: C11.2 D4.1 L2.1 U3.10 | length 35.4
  Top Layer w10: U3.10@1958.6,735.17 1994,735.17
NetC12_1: C12.1 J4.4 R10.2 | length 174.7
  Top Layer w15: R10.2@530.5,511 590.7,511 596.5,505.2 597.5,506.2 597.5,448.7 J4.4@564,415.2
NetC14_1: C14.1 R15.2 R16.1 | length 134.1
  Top Layer w10: C14.1@448.97,1034.79 R16.1@515.98,1034.79 R15.2@515.98,969.79
  Top Layer w15: C14.1@447.48,1033.3 C14.1@448.97,1034.79
NetC15_1: C15.1 R16.2 R17.1 | length 135.3
  Top Layer w15: R16.2@578.97,1034.79 572.62,1041.14 C15.1@572.62,1096 572.62,1158.44 R17.1@578.97,1164.79
NetC16_1: C16.1 R17.2 R18.1 | length 131.7
  Top Layer w10: R17.2@515.98,1164.79 C16.1@515.97,1231.79 R18.1@578.29,1231.79
  Top Layer w15: R18.1@578.29,1231.79 R18.1@580,1233.5
NetC17_1: C17.1 R18.2 U2.3 | length 144.3
  Top Layer w10: C17.1@501.36,1296.79 R18.2@579.7,1296.79 ; U2.3@509.46,1359.64 509.46,1304.04 C17.1@516.5,1297
  Top Layer w15: R18.2@579.7,1296.79 R18.2@580,1296.5
NetC19_1: C19.1 C25.1 D3.2 J7.2 L2.2 TP8.1
  other v1: 2473,1329.8 2513,1329.8 2553,1329.8 2471,1365.8 2511,1365.8 2551,1365.8
NetC19_2: C19.2 C25.2 J7.1 R11.1 R14.2 TP11.1
  other v1: 2470,1077.8 2510,1077.8 2550,1077.8 2468,1113.8 2508,1113.8 2548,1113.8
NetC27_1: C27.1 U3.8 | length 108.2
  Top Layer w10: U3.8@1958.6,695.8 C27.1@2066.77,695.8
NetC30_1: C30.1 R24.2 U4.3 | length 141.4
  Top Layer w10: U4.3@845.9,1356.12 845.9,1295.35 847,1294.25 925.75,1294.25 R24.2@926,1294.5
NetC31_1: C31.1 R24.1 R25.2 | length 133.9
  Top Layer w10: R25.2@862,1160.25 C31.1@862,1229.25 ; C31.1@864.25,1231.5 R24.1@926,1231.5
  Top Layer w12: C31.1@862,1229.25 C31.1@864.25,1231.5
NetC32_1: C32.1 R25.1 R26.2 | length 130.8
  Top Layer w10: R26.2@925,1032.25 921.62,1035.62 C32.1@921.62,1095 921.62,1156.88 R25.1@925,1160.25
NetC33_1: C33.1 R26.1 R27.2 | length 135.4
  Top Layer w10: R27.2@797,962.25 C33.1@797,1032.5 797.25,1032.25 R26.1@862,1032.25
NetC34_1: C34.1 R29.1 | length 70.1
  Top Layer w10: R29.1@1754.5,1745 1756,1743.5 C34.1@1756,1675.5
NetC35_1: C35.1 R30.1 | length 66.8
  Top Layer w10: C35.1@1754.5,509.99 R30.1@1754.5,576.8
NetJ2_2: J2.2 R20.2 | length 100.6
  Top Layer w10: J2.2@1027,412.43 1027,510.93 R20.2@1028.5,512.43
NetR1_1: R1.1 R6.2 TP4.1 U1.3 | length 413.8
  Top Layer w10: TP4.1@1437,1864 1437.5,1863.5 R1.1@1621,1863.5 ; R6.2@1621,1796.5 R1.1@1621,1863.5 ; U1.3@1783.4,1864 1621.5,1864 R1.1@1621,1863.5
NetR2_2: R2.2 U1.4 | length 117.2
  Top Layer w10: R2.2@1686,1796.5 1686.5,1796.5 1734.32,1844.32 U1.4@1783.4,1844.32
NetR3_2: R3.2 U1.7 | length 213.7
  Top Layer w10: U1.7@1958.6,1844.32 2020.69,1844.32 2049.5,1815.5 2096,1815.5 R3.2@2141.5,1861
NetR5_2: R5.2 R29.2 U1.5 | length 164.5
  Top Layer w10: U1.5@1783.4,1824.63 1783.4,1779.09 R29.2@1817.5,1745 1817.5,1675 R5.2@1818,1674.5
NetR8_1: R8.1 R13.2 TP10.1 U3.3 | length 413.5
  Top Layer w10: TP10.1@1437,694 1619.7,694 R8.1@1621,695.3 R13.2@1621,628.3 ; R8.1@1621.5,695.8 U3.3@1783.4,695.8
NetR9_2: R9.2 U3.4 | length 116.7
  Top Layer w10: R9.2@1686.5,628.3 1734.32,676.11 U3.4@1783.4,676.11
NetR11_2: R11.2 U3.7 | length 211.2
  Top Layer w10: U3.7@1958.6,676.11 2020.69,676.11 2047.9,648.9 2100.4,648.9 R11.2@2141.5,690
